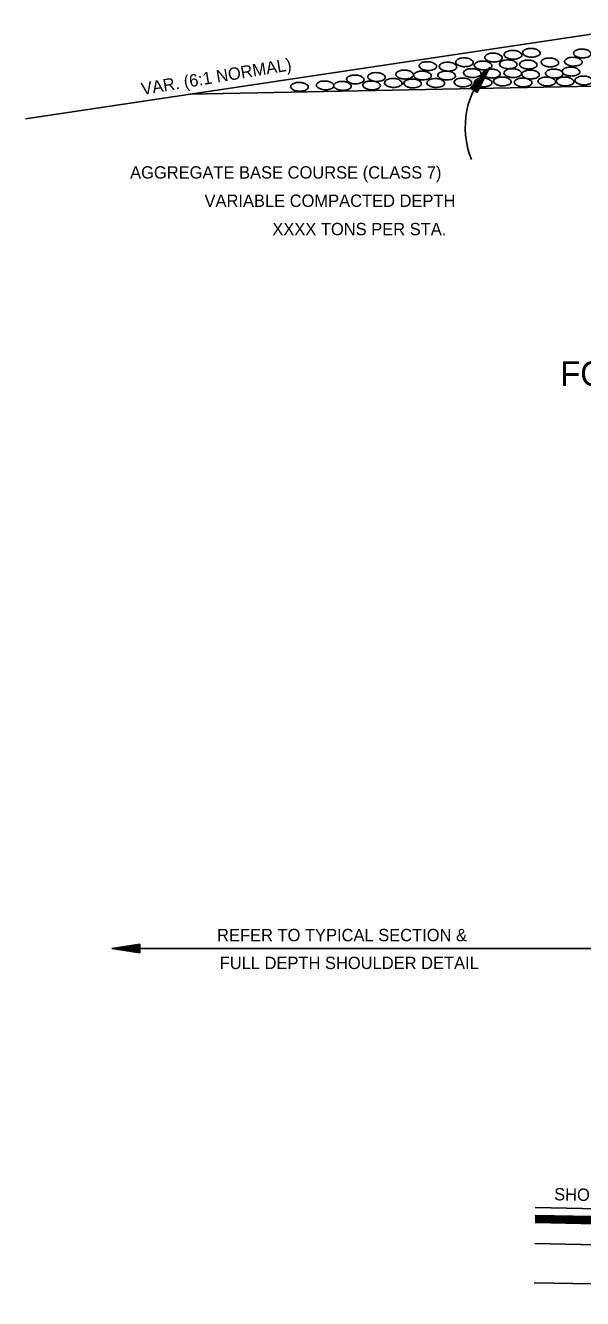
# Model space of a CAD drawing. Extents: x 635488 to 635865, y 290537 to 290973.
# Drawn here: x 635487.8 to 635514.9, y 290830 to 290891.9 of the extents above; entities that cross this region are included whole.
import ezdxf

# ---------------------------------------------------------------- set-up
doc = ezdxf.new("R2010")
doc.units = 0
doc.layers.add('Default', color=7, linetype='Continuous')

msp = doc.modelspace()

# ---------------------------------------------------------------- linework, layer by layer
at = {"layer": 'Default'}
for p, q in [((635518.177, 290891.946), (635487.759, 290887.399)), ((635540.634, 290889.491), (635495.751, 290888.594)), ((635509.42, 290888.914), (635510.37, 290889.919)), ((635509.448, 290888.89), (635510.238, 290889.732)), ((635509.477, 290888.873), (635510.104, 290889.537)), ((635509.7, 290888.716), (635510.104, 290889.537)), ((635509.73, 290888.695), (635510.238, 290889.732)), ((635509.758, 290888.677), (635510.37, 290889.919)), ((635509.758, 290888.677), (635509.42, 290888.914)), ((635509.506, 290888.851), (635509.975, 290889.35)), ((635509.534, 290888.833), (635509.841, 290889.16)), ((635509.563, 290888.812), (635509.711, 290888.974)), ((635509.615, 290888.775), (635509.711, 290888.974)), ((635509.643, 290888.758), (635509.841, 290889.16)), ((635509.671, 290888.736), (635509.975, 290889.35)), ((635493.327, 290847.21), (635491.959, 290847.005)), ((635519.824, 290847.005), (635491.959, 290847.005)), ((635493.327, 290846.799), (635491.959, 290847.005)), ((635493.327, 290847.174), (635492.186, 290847.005)), ((635493.327, 290846.833), (635492.186, 290847.005)), ((635493.327, 290847.14), (635492.42, 290847.005)), ((635493.327, 290846.867), (635492.42, 290847.005)), ((635493.327, 290847.107), (635492.647, 290847.005)), ((635493.327, 290846.902), (635492.647, 290847.005)), ((635493.327, 290847.07), (635492.88, 290847.005)), ((635493.327, 290846.939), (635492.88, 290847.005)), ((635493.327, 290847.036), (635493.11, 290847.005)), ((635493.327, 290846.97), (635493.11, 290847.005)), ((635493.327, 290846.799), (635493.327, 290847.21)), ((635512.581, 290834.008), (635519.442, 290833.873)), ((635512.581, 290833.966), (635519.442, 290833.829)), ((635512.581, 290833.934), (635519.442, 290833.796)), ((635512.581, 290833.893), (635519.442, 290833.754)), ((635512.581, 290833.853), (635519.442, 290833.712)), ((635512.581, 290833.815), (635519.442, 290833.676)), ((635512.581, 290833.776), (635519.442, 290833.638)), ((635512.581, 290833.737), (635519.442, 290833.6)), ((635512.581, 290833.694), (635519.442, 290833.558)), ((635512.581, 290833.656), (635519.442, 290833.521)), ((635512.561, 290832.64), (635519.422, 290832.505)), ((635512.523, 290830.734), (635551.153, 290829.962))]:
    msp.add_line(p, q, dxfattribs=at)
msp.add_lwpolyline([(635512.581, 290834.39), (635519.442, 290834.253), (635519.833, 290833.858)], dxfattribs=at)
msp.add_arc((635513.355, 290886.987), 4.183, 135.51784, 202.00677, dxfattribs=at)
for points in [[(635511.501, 290890.724), (635511.351, 290890.723), (635511.171, 290890.661), (635511.08, 290890.576), (635511.065, 290890.523), (635511.114, 290890.43), (635511.167, 290890.391), (635511.266, 290890.341), (635511.414, 290890.307), (635511.49, 290890.301), (635511.602, 290890.308), (635511.724, 290890.329), (635511.819, 290890.368), (635511.909, 290890.439), (635511.925, 290890.497), (635511.895, 290890.58), (635511.827, 290890.634), (635511.763, 290890.678), (635511.661, 290890.712), (635511.598, 290890.723), (635511.501, 290890.724)], [(635512.398, 290890.823), (635512.246, 290890.821), (635512.065, 290890.76), (635511.975, 290890.673), (635511.961, 290890.622), (635512.009, 290890.53), (635512.062, 290890.489), (635512.159, 290890.441), (635512.308, 290890.405), (635512.383, 290890.396), (635512.495, 290890.407), (635512.618, 290890.427), (635512.715, 290890.466), (635512.802, 290890.536), (635512.818, 290890.595), (635512.79, 290890.678), (635512.721, 290890.731), (635512.657, 290890.776), (635512.554, 290890.807), (635512.494, 290890.821), (635512.398, 290890.823)], [(635514.876, 290890.788), (635514.727, 290890.787), (635514.546, 290890.724), (635514.455, 290890.637), (635514.44, 290890.589), (635514.488, 290890.495), (635514.543, 290890.452), (635514.641, 290890.407), (635514.789, 290890.371), (635514.864, 290890.363), (635514.973, 290890.372), (635515.099, 290890.393), (635515.193, 290890.43), (635515.284, 290890.5), (635515.297, 290890.561), (635515.269, 290890.643), (635515.2, 290890.698), (635515.138, 290890.742), (635515.037, 290890.771), (635514.971, 290890.787), (635514.876, 290890.788)], [(635507.359, 290890.176), (635507.205, 290890.174), (635507.024, 290890.112), (635506.935, 290890.026), (635506.924, 290889.975), (635506.971, 290889.881), (635507.022, 290889.841), (635507.119, 290889.791), (635507.269, 290889.758), (635507.343, 290889.747), (635507.456, 290889.76), (635507.577, 290889.78), (635507.674, 290889.816), (635507.763, 290889.889), (635507.778, 290889.948), (635507.75, 290890.031), (635507.682, 290890.084), (635507.616, 290890.128), (635507.518, 290890.159), (635507.454, 290890.174), (635507.359, 290890.176)], [(635508.336, 290890.153), (635508.183, 290890.149), (635508.004, 290890.089), (635507.914, 290890), (635507.9, 290889.952), (635507.948, 290889.858), (635508.003, 290889.816), (635508.098, 290889.769), (635508.249, 290889.732), (635508.322, 290889.726), (635508.434, 290889.735), (635508.556, 290889.758), (635508.652, 290889.793), (635508.741, 290889.864), (635508.757, 290889.925), (635508.729, 290890.009), (635508.66, 290890.062), (635508.595, 290890.104), (635508.493, 290890.137), (635508.433, 290890.149), (635508.336, 290890.153)], [(635509.143, 290890.363), (635508.992, 290890.361), (635508.811, 290890.301), (635508.721, 290890.215), (635508.708, 290890.163), (635508.757, 290890.067), (635508.807, 290890.029), (635508.905, 290889.98), (635509.053, 290889.942), (635509.129, 290889.936), (635509.24, 290889.947), (635509.364, 290889.967), (635509.461, 290890.006), (635509.55, 290890.075), (635509.564, 290890.135), (635509.536, 290890.218), (635509.466, 290890.271), (635509.403, 290890.313), (635509.304, 290890.347), (635509.238, 290890.361), (635509.143, 290890.363)], [(635510.049, 290890.207), (635509.897, 290890.204), (635509.717, 290890.143), (635509.628, 290890.056), (635509.614, 290890.009), (635509.664, 290889.914), (635509.715, 290889.874), (635509.812, 290889.825), (635509.961, 290889.788), (635510.036, 290889.782), (635510.147, 290889.789), (635510.27, 290889.81), (635510.366, 290889.849), (635510.455, 290889.919), (635510.471, 290889.98), (635510.441, 290890.062), (635510.373, 290890.118), (635510.309, 290890.159), (635510.211, 290890.19), (635510.145, 290890.204), (635510.049, 290890.207)], [(635510.557, 290890.592), (635510.405, 290890.589), (635510.222, 290890.528), (635510.133, 290890.441), (635510.12, 290890.391), (635510.169, 290890.296), (635510.22, 290890.257), (635510.318, 290890.207), (635510.466, 290890.173), (635510.541, 290890.165), (635510.653, 290890.174), (635510.776, 290890.196), (635510.873, 290890.234), (635510.962, 290890.304), (635510.974, 290890.363), (635510.949, 290890.446), (635510.879, 290890.499), (635510.815, 290890.542), (635510.716, 290890.576), (635510.65, 290890.589), (635510.557, 290890.592)], [(635511.27, 290890.265), (635511.122, 290890.262), (635510.938, 290890.201), (635510.851, 290890.114), (635510.836, 290890.064), (635510.885, 290889.97), (635510.937, 290889.93), (635511.037, 290889.881), (635511.181, 290889.846), (635511.261, 290889.838), (635511.368, 290889.847), (635511.495, 290889.867), (635511.59, 290889.906), (635511.679, 290889.976), (635511.693, 290890.036), (635511.663, 290890.12), (635511.594, 290890.174), (635511.534, 290890.218), (635511.432, 290890.249), (635511.367, 290890.262), (635511.27, 290890.265)], [(635512.249, 290890.251), (635512.098, 290890.249), (635511.914, 290890.187), (635511.827, 290890.101), (635511.813, 290890.051), (635511.861, 290889.956), (635511.912, 290889.916), (635512.012, 290889.867), (635512.159, 290889.83), (635512.235, 290889.825), (635512.346, 290889.833), (635512.47, 290889.855), (635512.567, 290889.894), (635512.656, 290889.964), (635512.668, 290890.022), (635512.64, 290890.104), (635512.571, 290890.159), (635512.509, 290890.202), (635512.408, 290890.237), (635512.344, 290890.249), (635512.249, 290890.251)], [(635513.301, 290890.354), (635513.15, 290890.352), (635512.966, 290890.29), (635512.878, 290890.202), (635512.866, 290890.153), (635512.911, 290890.061), (635512.964, 290890.017), (635513.064, 290889.97), (635513.212, 290889.934), (635513.285, 290889.927), (635513.399, 290889.936), (635513.524, 290889.956), (635513.616, 290889.995), (635513.707, 290890.065), (635513.72, 290890.125), (635513.692, 290890.207), (635513.625, 290890.262), (635513.561, 290890.307), (635513.46, 290890.338), (635513.396, 290890.352), (635513.301, 290890.354)], [(635514.446, 290890.393), (635514.298, 290890.391), (635514.114, 290890.329), (635514.025, 290890.241), (635514.01, 290890.19), (635514.06, 290890.1), (635514.113, 290890.056), (635514.211, 290890.011), (635514.36, 290889.972), (635514.435, 290889.967), (635514.547, 290889.975), (635514.669, 290889.995), (635514.764, 290890.034), (635514.854, 290890.104), (635514.868, 290890.165), (635514.84, 290890.245), (635514.773, 290890.302), (635514.708, 290890.346), (635514.607, 290890.375), (635514.546, 290890.391), (635514.446, 290890.393)], [(635503.828, 290889.526), (635503.677, 290889.525), (635503.494, 290889.461), (635503.402, 290889.375), (635503.388, 290889.325), (635503.438, 290889.232), (635503.491, 290889.19), (635503.588, 290889.141), (635503.739, 290889.104), (635503.812, 290889.099), (635503.926, 290889.107), (635504.048, 290889.129), (635504.143, 290889.168), (635504.231, 290889.238), (635504.245, 290889.3), (635504.219, 290889.378), (635504.15, 290889.434), (635504.085, 290889.478), (635503.987, 290889.511), (635503.924, 290889.525), (635503.828, 290889.526)], [(635504.861, 290889.646), (635504.71, 290889.645), (635504.528, 290889.581), (635504.436, 290889.495), (635504.422, 290889.445), (635504.471, 290889.352), (635504.524, 290889.31), (635504.621, 290889.261), (635504.772, 290889.224), (635504.845, 290889.219), (635504.959, 290889.227), (635505.081, 290889.249), (635505.176, 290889.288), (635505.265, 290889.358), (635505.279, 290889.42), (635505.252, 290889.498), (635505.184, 290889.554), (635505.118, 290889.598), (635505.02, 290889.631), (635504.958, 290889.645), (635504.861, 290889.646)], [(635506.232, 290889.766), (635506.081, 290889.765), (635505.899, 290889.701), (635505.807, 290889.615), (635505.793, 290889.565), (635505.843, 290889.472), (635505.896, 290889.43), (635505.992, 290889.381), (635506.143, 290889.344), (635506.217, 290889.339), (635506.33, 290889.347), (635506.452, 290889.369), (635506.547, 290889.408), (635506.636, 290889.478), (635506.65, 290889.54), (635506.623, 290889.618), (635506.555, 290889.674), (635506.489, 290889.718), (635506.391, 290889.751), (635506.329, 290889.765), (635506.232, 290889.766)], [(635507.099, 290889.718), (635506.948, 290889.716), (635506.765, 290889.652), (635506.673, 290889.567), (635506.659, 290889.517), (635506.709, 290889.423), (635506.762, 290889.381), (635506.859, 290889.333), (635507.01, 290889.296), (635507.083, 290889.291), (635507.197, 290889.299), (635507.318, 290889.32), (635507.413, 290889.359), (635507.502, 290889.43), (635507.516, 290889.492), (635507.49, 290889.57), (635507.421, 290889.626), (635507.356, 290889.669), (635507.258, 290889.702), (635507.195, 290889.716), (635507.099, 290889.718)], [(635508.277, 290889.718), (635508.126, 290889.716), (635507.943, 290889.652), (635507.851, 290889.567), (635507.837, 290889.517), (635507.887, 290889.423), (635507.94, 290889.381), (635508.037, 290889.333), (635508.188, 290889.296), (635508.261, 290889.291), (635508.375, 290889.299), (635508.497, 290889.32), (635508.592, 290889.359), (635508.68, 290889.43), (635508.694, 290889.492), (635508.668, 290889.57), (635508.599, 290889.626), (635508.534, 290889.669), (635508.436, 290889.702), (635508.373, 290889.716), (635508.277, 290889.718)], [(635509.527, 290889.838), (635509.375, 290889.836), (635509.193, 290889.772), (635509.101, 290889.687), (635509.087, 290889.637), (635509.137, 290889.543), (635509.19, 290889.501), (635509.287, 290889.453), (635509.438, 290889.415), (635509.511, 290889.411), (635509.625, 290889.419), (635509.746, 290889.44), (635509.841, 290889.479), (635509.93, 290889.55), (635509.944, 290889.612), (635509.918, 290889.69), (635509.849, 290889.746), (635509.784, 290889.789), (635509.685, 290889.822), (635509.623, 290889.836), (635509.527, 290889.838)], [(635510.463, 290889.814), (635510.312, 290889.813), (635510.13, 290889.749), (635510.038, 290889.663), (635510.024, 290889.613), (635510.074, 290889.52), (635510.126, 290889.478), (635510.223, 290889.43), (635510.374, 290889.392), (635510.447, 290889.387), (635510.561, 290889.395), (635510.683, 290889.417), (635510.778, 290889.456), (635510.867, 290889.526), (635510.881, 290889.588), (635510.854, 290889.666), (635510.786, 290889.722), (635510.72, 290889.766), (635510.622, 290889.799), (635510.56, 290889.813), (635510.463, 290889.814)], [(635511.496, 290889.838), (635511.345, 290889.836), (635511.163, 290889.772), (635511.071, 290889.687), (635511.057, 290889.637), (635511.107, 290889.543), (635511.16, 290889.501), (635511.256, 290889.453), (635511.407, 290889.415), (635511.481, 290889.411), (635511.594, 290889.419), (635511.716, 290889.44), (635511.811, 290889.479), (635511.9, 290889.55), (635511.914, 290889.612), (635511.887, 290889.69), (635511.819, 290889.746), (635511.753, 290889.789), (635511.655, 290889.822), (635511.593, 290889.836), (635511.496, 290889.838)], [(635512.361, 290889.766), (635512.21, 290889.765), (635512.028, 290889.701), (635511.936, 290889.615), (635511.922, 290889.565), (635511.972, 290889.472), (635512.024, 290889.43), (635512.121, 290889.381), (635512.272, 290889.344), (635512.346, 290889.339), (635512.459, 290889.347), (635512.581, 290889.369), (635512.676, 290889.408), (635512.765, 290889.478), (635512.779, 290889.54), (635512.752, 290889.618), (635512.684, 290889.674), (635512.618, 290889.718), (635512.52, 290889.751), (635512.458, 290889.765), (635512.361, 290889.766)], [(635513.514, 290889.814), (635513.363, 290889.813), (635513.181, 290889.749), (635513.089, 290889.663), (635513.075, 290889.613), (635513.125, 290889.52), (635513.178, 290889.478), (635513.274, 290889.43), (635513.425, 290889.392), (635513.499, 290889.387), (635513.612, 290889.395), (635513.734, 290889.417), (635513.829, 290889.456), (635513.918, 290889.526), (635513.932, 290889.588), (635513.905, 290889.666), (635513.837, 290889.722), (635513.771, 290889.766), (635513.673, 290889.799), (635513.611, 290889.813), (635513.514, 290889.814)], [(635514.331, 290889.911), (635514.18, 290889.909), (635513.997, 290889.846), (635513.905, 290889.76), (635513.891, 290889.71), (635513.941, 290889.617), (635513.994, 290889.574), (635514.091, 290889.526), (635514.242, 290889.489), (635514.315, 290889.484), (635514.429, 290889.492), (635514.55, 290889.514), (635514.646, 290889.553), (635514.734, 290889.623), (635514.748, 290889.685), (635514.722, 290889.763), (635514.653, 290889.819), (635514.588, 290889.863), (635514.49, 290889.895), (635514.427, 290889.909), (635514.331, 290889.911)], [(635514.956, 290889.478), (635514.804, 290889.476), (635514.622, 290889.412), (635514.53, 290889.327), (635514.516, 290889.277), (635514.566, 290889.183), (635514.619, 290889.141), (635514.716, 290889.093), (635514.867, 290889.056), (635514.94, 290889.051), (635515.054, 290889.059), (635515.175, 290889.08), (635515.27, 290889.119), (635515.359, 290889.19), (635515.373, 290889.252), (635515.347, 290889.33), (635515.278, 290889.386), (635515.213, 290889.43), (635515.115, 290889.462), (635515.052, 290889.476), (635514.956, 290889.478)], [(635501.112, 290889.166), (635500.961, 290889.165), (635500.778, 290889.101), (635500.686, 290889.015), (635500.672, 290888.965), (635500.722, 290888.872), (635500.775, 290888.83), (635500.872, 290888.781), (635501.023, 290888.744), (635501.096, 290888.739), (635501.21, 290888.747), (635501.331, 290888.769), (635501.426, 290888.808), (635501.515, 290888.878), (635501.529, 290888.94), (635501.503, 290889.018), (635501.434, 290889.074), (635501.369, 290889.118), (635501.271, 290889.151), (635501.208, 290889.165), (635501.112, 290889.166)], [(635502.361, 290889.238), (635502.21, 290889.236), (635502.028, 290889.172), (635501.936, 290889.087), (635501.922, 290889.037), (635501.972, 290888.943), (635502.025, 290888.901), (635502.121, 290888.853), (635502.273, 290888.816), (635502.346, 290888.811), (635502.46, 290888.819), (635502.581, 290888.84), (635502.676, 290888.879), (635502.765, 290888.95), (635502.779, 290889.012), (635502.753, 290889.09), (635502.684, 290889.146), (635502.619, 290889.19), (635502.52, 290889.222), (635502.458, 290889.236), (635502.361, 290889.238)], [(635503.203, 290889.213), (635503.052, 290889.211), (635502.869, 290889.147), (635502.778, 290889.062), (635502.764, 290889.012), (635502.813, 290888.918), (635502.866, 290888.876), (635502.963, 290888.828), (635503.114, 290888.791), (635503.187, 290888.786), (635503.301, 290888.794), (635503.423, 290888.816), (635503.518, 290888.855), (635503.607, 290888.925), (635503.621, 290888.987), (635503.594, 290889.065), (635503.526, 290889.121), (635503.46, 290889.165), (635503.362, 290889.197), (635503.3, 290889.211), (635503.203, 290889.213)], [(635504.621, 290889.238), (635504.47, 290889.236), (635504.288, 290889.172), (635504.196, 290889.087), (635504.182, 290889.037), (635504.231, 290888.943), (635504.284, 290888.901), (635504.381, 290888.853), (635504.532, 290888.816), (635504.605, 290888.811), (635504.719, 290888.819), (635504.841, 290888.84), (635504.936, 290888.879), (635505.025, 290888.95), (635505.039, 290889.012), (635505.012, 290889.09), (635504.944, 290889.146), (635504.878, 290889.19), (635504.78, 290889.222), (635504.718, 290889.236), (635504.621, 290889.238)], [(635505.679, 290889.358), (635505.528, 290889.356), (635505.346, 290889.292), (635505.254, 290889.207), (635505.24, 290889.157), (635505.29, 290889.063), (635505.343, 290889.021), (635505.439, 290888.973), (635505.59, 290888.936), (635505.664, 290888.931), (635505.777, 290888.939), (635505.899, 290888.96), (635505.994, 290888.999), (635506.083, 290889.07), (635506.097, 290889.132), (635506.07, 290889.21), (635506.002, 290889.266), (635505.936, 290889.31), (635505.838, 290889.342), (635505.776, 290889.356), (635505.679, 290889.358)], [(635506.617, 290889.333), (635506.466, 290889.331), (635506.284, 290889.267), (635506.192, 290889.182), (635506.178, 290889.132), (635506.228, 290889.038), (635506.281, 290888.996), (635506.377, 290888.948), (635506.528, 290888.911), (635506.602, 290888.906), (635506.715, 290888.914), (635506.837, 290888.936), (635506.932, 290888.974), (635507.021, 290889.045), (635507.035, 290889.107), (635507.008, 290889.185), (635506.94, 290889.241), (635506.874, 290889.285), (635506.776, 290889.317), (635506.714, 290889.331), (635506.617, 290889.333)], [(635507.749, 290889.356), (635507.597, 290889.355), (635507.415, 290889.291), (635507.323, 290889.205), (635507.309, 290889.155), (635507.359, 290889.062), (635507.412, 290889.02), (635507.509, 290888.971), (635507.66, 290888.934), (635507.733, 290888.929), (635507.847, 290888.937), (635507.968, 290888.959), (635508.063, 290888.998), (635508.152, 290889.068), (635508.166, 290889.13), (635508.14, 290889.208), (635508.071, 290889.264), (635508.006, 290889.308), (635507.907, 290889.341), (635507.845, 290889.355), (635507.749, 290889.356)], [(635509.07, 290889.381), (635508.919, 290889.38), (635508.736, 290889.316), (635508.645, 290889.23), (635508.631, 290889.18), (635508.68, 290889.087), (635508.733, 290889.045), (635508.83, 290888.996), (635508.981, 290888.959), (635509.054, 290888.954), (635509.168, 290888.962), (635509.29, 290888.984), (635509.385, 290889.023), (635509.474, 290889.093), (635509.488, 290889.155), (635509.461, 290889.233), (635509.393, 290889.289), (635509.327, 290889.333), (635509.229, 290889.366), (635509.167, 290889.38), (635509.07, 290889.381)], [(635510.055, 290889.381), (635509.904, 290889.38), (635509.721, 290889.316), (635509.629, 290889.23), (635509.615, 290889.18), (635509.665, 290889.087), (635509.718, 290889.045), (635509.815, 290888.996), (635509.966, 290888.959), (635510.039, 290888.954), (635510.153, 290888.962), (635510.275, 290888.984), (635510.37, 290889.023), (635510.458, 290889.093), (635510.472, 290889.155), (635510.446, 290889.233), (635510.377, 290889.289), (635510.312, 290889.333), (635510.214, 290889.366), (635510.151, 290889.38), (635510.055, 290889.381)], [(635510.991, 290889.43), (635510.84, 290889.428), (635510.658, 290889.364), (635510.566, 290889.278), (635510.552, 290889.228), (635510.602, 290889.135), (635510.655, 290889.093), (635510.751, 290889.045), (635510.903, 290889.007), (635510.976, 290889.003), (635511.09, 290889.01), (635511.211, 290889.032), (635511.306, 290889.071), (635511.395, 290889.141), (635511.409, 290889.204), (635511.382, 290889.281), (635511.314, 290889.338), (635511.248, 290889.381), (635511.15, 290889.414), (635511.088, 290889.428), (635510.991, 290889.43)], [(635512.001, 290889.381), (635511.85, 290889.38), (635511.668, 290889.316), (635511.576, 290889.23), (635511.562, 290889.18), (635511.612, 290889.087), (635511.665, 290889.045), (635511.761, 290888.996), (635511.912, 290888.959), (635511.986, 290888.954), (635512.099, 290888.962), (635512.221, 290888.984), (635512.316, 290889.023), (635512.405, 290889.093), (635512.419, 290889.155), (635512.392, 290889.233), (635512.324, 290889.289), (635512.258, 290889.333), (635512.16, 290889.366), (635512.098, 290889.38), (635512.001, 290889.381)], [(635513.154, 290889.43), (635513.003, 290889.428), (635512.821, 290889.364), (635512.729, 290889.278), (635512.715, 290889.228), (635512.765, 290889.135), (635512.818, 290889.093), (635512.914, 290889.045), (635513.065, 290889.007), (635513.139, 290889.003), (635513.252, 290889.01), (635513.374, 290889.032), (635513.469, 290889.071), (635513.558, 290889.141), (635513.572, 290889.204), (635513.545, 290889.281), (635513.477, 290889.338), (635513.411, 290889.381), (635513.313, 290889.414), (635513.251, 290889.428), (635513.154, 290889.43)], [(635514.042, 290889.43), (635513.891, 290889.428), (635513.709, 290889.364), (635513.617, 290889.278), (635513.603, 290889.228), (635513.653, 290889.135), (635513.706, 290889.093), (635513.803, 290889.045), (635513.954, 290889.007), (635514.027, 290889.003), (635514.141, 290889.01), (635514.262, 290889.032), (635514.357, 290889.071), (635514.446, 290889.141), (635514.46, 290889.204), (635514.434, 290889.281), (635514.365, 290889.338), (635514.3, 290889.381), (635514.201, 290889.414), (635514.139, 290889.428), (635514.042, 290889.43)]]:
    msp.add_spline(points, degree=3, dxfattribs=at)

# ---------------------------------------------------------------- texts
for s, rotation, p in [('VAR. (6:1 NORMAL)', 9.46161, (635493.449, 290888.553)), ('SHOULDER', 358.85424, (635513.497, 290834.746))]:
    msp.add_text(s, height=0.6, rotation=rotation, dxfattribs=at).set_placement(p)
for s, height, p in [('AGGREGATE BASE COURSE (CLASS 7)', 0.6, (635492.855, 290884.491)), ('VARIABLE COMPACTED DEPTH', 0.6, (635496.478, 290883.112)), ('XXXX TONS PER STA.', 0.6, (635499.78, 290881.733)), ('FOR MAINTENANCE OF TRAFFIC', 1.2, (635513.796, 290874.396)), ('REFER TO TYPICAL SECTION &', 0.6, (635497.089, 290847.359)), ('FULL DEPTH SHOULDER DETAIL', 0.6, (635497.216, 290846.003))]:
    msp.add_text(s, height=height, dxfattribs=at).set_placement(p)

doc.saveas('drawing.dxf')
